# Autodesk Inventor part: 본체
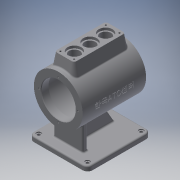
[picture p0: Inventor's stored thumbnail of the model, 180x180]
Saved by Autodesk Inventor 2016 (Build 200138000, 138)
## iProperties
Created: 2015-11
Part Number: 본체
Material: 알루미늄 6061
Document SubType Name: Modeling
Designer: mduedu
Density: 2.71 g/cm^3
Mass: 1557.05 g
Surface Area: 1415.53 cm^2
Volume: 574.559 cm^3
Appearance: 기본값
Author: mduedu
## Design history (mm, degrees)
sketch "스케치2"
  geometry: C1 r 50 at (0, 0); 1 further point
  constraints: 1 centre point, 1 coincident
  dimensions: "d147" = 100 diameter of C1
extrude "돌출1" new body sketch "스케치2" stored distance "d12" = 130; taper "d13" = 0 deg
feature "쉘1" dims "d31" = 15, "d32" = 6, "d33" = 15
sketch "스케치5"
  geometry: C1 r 35 at (0, 0); 1 further point
  constraints: 1 centre point, 1 coincident
  dimensions: "d34" = 70 diameter of C1
extrude "돌출3" cut sketch "스케치5" stored distance "d36" = 3; taper "d37" = 0 deg
node "작업 평면1"
sketch "스케치6"
  geometry: L1 (-65, -60)-(65, -60); L2 (65, -60)-(65, 60); L3 (65, 60)-(-65, 60); L4 (-65, 60)-(-65, -60); L5 (-65, -60)-(65, 60); L6 (65, -60)-(-65, 60); 1 further point
  constraints: 12 end point, 2 midpoint, 2 parallel, 1 horizontal, 1 perpendicular
  dimensions: "d41" = 120 distance of L3.end L1.start; "d43" = 130 distance of L2.end L3.end
extrude "돌출4" join sketch "스케치6" distance "d44" = 10; taper "d45" = 0 deg
sketch "스케치19"
  geometry: L1 (-45, 30)-(-35, 30); L2 (-35, 30)-(-35, -30); L3 (-35, -30)-(-45, -30); L4 (-45, -30)-(-45, 30); L5 (-65, 60)-(-65, -60) reference; 2 further points
  constraints: 8 end point, 2 parallel, 1 horizontal, 1 horizontal alignment, 1 midpoint, 1 perpendicular
  dimensions: "d150" = 20 distance between parallel lines of L4 L5; "d151" = 10 distance of L1.start L1.end; "d152" = 60 distance of L3.end L1.start
extrude "돌출9" join sketch "스케치19" stored distance "d153" = 10; taper "d154" = 0 deg
sketch "스케치20"
  geometry: L1 (65, 35)-(50, 35) reference; L2 (50, 35)-(50, 44) reference; L3 (50, 44)-(-50, 44) reference; L4 (-50, 44)-(-50, 35) reference; L5 (-50, 35)-(-65, 35) reference; L6 (-65, 35)-(-65, 50) reference; L7 (-65, 50)-(65, 50) reference; L8 (65, 50)-(65, 35) reference; L9 (50, -35)-(65, -35) reference; L10 (65, -35)-(65, -50) reference; L11 (65, -50)-(45, -50) reference; L12 (45, -50)-(45, -90) reference; L13 (45, -90)-(65, -90) reference; L14 (65, -90)-(65, -100) reference; L15 (65, -100)-(-65, -100) reference; L16 (-65, -100)-(-65, -90) reference; L17 (-65, -90)-(35, -90) reference; L18 (35, -90)-(35, -50) reference; L19 (35, -50)-(-65, -50) reference; L20 (-65, -50)-(-65, -35) reference; L21 (-65, -35)-(-50, -35) reference; L22 (-50, -35)-(-50, -44) reference; L23 (-50, -44)-(50, -44) reference; L24 (50, -44)-(50, -35) reference; L25 (-45, -90)-(-21.906, -50); 1 further point
  constraints: 2 end point, 2 point on line
  dimensions: "d155" = 20 distance from line of L25.start L16; "d156" = 120 deg angle of L25 L17
feature "리브2" sketch "스케치20" dims "d157" = 1, "d158" = 10, "d159" = 0, "d160" = 0, "d161" = 1, "d162" = 1
fillet "모깎기21" dims "d163" = 3
fillet "모깎기22" dims "d164" = 3
fillet "모깎기23" dims "d165" = 3
sketch "스케치21" dims "d166" = 80
  geometry: 3 further points
  constraints: 2 horizontal alignment, 1 coincident, 2 other
hole "구멍6" sketch "스케치21" at (40, 0) diameter "d168" = 3.242; stored, may be unused: countersink angle "d172" = 90 deg, drill point angle "d174" = 118 deg; dims "d169" = 9, "d170" = 4, "d171" = 2, "d173" = 11
node "작업 평면2"
sketch "스케치13"
  geometry: L1 (-52.5, -20)-(52.5, -20); L2 (52.5, -20)-(52.5, 20); L3 (52.5, 20)-(-52.5, 20); L4 (-52.5, 20)-(-52.5, -20); L5 (-52.5, -20)-(52.5, 20); L6 (52.5, -20)-(-52.5, 20); 1 further point
  constraints: 12 end point, 2 midpoint, 2 parallel, 1 horizontal, 1 perpendicular
  dimensions: "d93" = 105 distance of L2.end L3.end; "d95" = 40 distance of L1.end L2.end
extrude "돌출8" join sketch "스케치13" stored distance "d96" = 80; taper "d97" = 0 deg
fillet "모깎기15" dims "d98" = 5
feature "면 기울기1" dims angle "d178" = 10 deg
fillet "모깎기24" dims "d179" = 3
sketch "스케치14"
  geometry: L1 (-52.5, 15)-(-52.5, -15) reference; L2 (52.5, -15)-(52.5, 15) reference; L3 (-52.5, 0)-(52.5, 0); 4 further points
  constraints: 2 end point, 2 midpoint, 2 point on line, 1 coincident
  dimensions: "d100" = 32 distance of point (-32, 0) point (0, 0); "d102" = 32 distance of point (32, 0) point (0, 0) (derived)
hole "구멍3" sketch "스케치14" at (-32, 0), (0, 0), (32, 0) diameter "d103" = 22; stored, may be unused: countersink angle "d107" = 90 deg, drill point angle "d109" = 118 deg; dims "d104" = 8, "d105" = 28, "d106" = 5, "d108" = 10
sketch "스케치15"
  geometry: L1 (46.5, -14)-(-46.5, -14); L2 (-46.5, -14)-(-46.5, 14); L3 (-46.5, 14)-(46.5, 14); L4 (46.5, 14)-(46.5, -14); L5 (46.5, -14)-(-46.5, 14); L6 (-46.5, -14)-(46.5, 14); L7 (47.5, 20)-(-47.5, 20) reference; L8 (-52.5, 15)-(-52.5, -15) reference; 5 further points
  constraints: 12 end point, 4 coincident, 2 midpoint, 2 parallel, 1 horizontal, 1 perpendicular
  dimensions: "d110" = 6 distance between parallel lines of L3 L7; "d111" = 6 distance between parallel lines of L2 L8
hole "구멍4" sketch "스케치15" at (-46.5, 14), (46.5, 14), (46.5, -14), (-46.5, -14) diameter "d112" = 3.242; stored, may be unused: countersink angle "d116" = 90 deg, drill point angle "d118" = 118 deg; dims "d113" = 10, "d114" = 28, "d115" = 5, "d117" = 13
node "작업 평면3"
sketch "스케치22"
  geometry: 2 further points
  constraints: 1 coincident, 1 other
feature "엠보싱3" sketch "스케치22" dims "d32" = 6, "d181" = 0.5, "d182" = 0
chamfer "모따기2" distance "d183" = 1; stored, may be unused: second distance "d184" = 2, angle "d185" = 45 deg
fillet "모깎기25" dims "d186" = 10
sketch "스케치23"
  geometry: L1 (55, 60)-(-55, 60) reference; L2 (65, -50)-(65, 50) reference; L3 (-55, -60)-(55, -60) reference; L4 (-65, 50)-(-65, -50) reference; A1 r 10 centre (-55, 50) between (-55, 60) and (-65, 50) reference; A2 r 10 centre (55, 50) between (65, 50) and (55, 60) reference; A3 r 10 centre (55, -50) between (55, -60) and (65, -50) reference; A4 r 10 centre (-55, -50) between (-65, -50) and (-55, -60) reference; 1 further point
hole "구멍7" sketch "스케치23" at (-55, 50), (-55, -50), (55, -50), (55, 50) diameter "d187" = 6; stored, may be unused: countersink angle "d191" = 90 deg, drill point angle "d193" = 118 deg; dims "d188" = 9, "d189" = 10, "d190" = 2, "d192" = 11
fillet "모깎기26" dims "d194" = 3
node "솔리드1"
pattern_circular "원형 패턴2" dims angle "d176" = 360 deg
mirror "대칭5"
node "투영된 루프2"
node "절단 모서리 투영1"
